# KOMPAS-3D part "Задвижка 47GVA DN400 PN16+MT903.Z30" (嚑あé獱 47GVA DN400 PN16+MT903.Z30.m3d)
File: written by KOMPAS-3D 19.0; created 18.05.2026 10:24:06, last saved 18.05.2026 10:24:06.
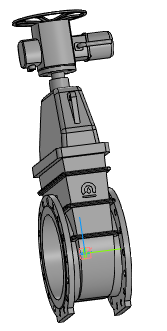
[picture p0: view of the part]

Document properties: Автор: Энергия; Полное имя файла: ..\Задвижка 47GVA DN50_DN1000+MT903.Z\Задвижка 47GVA DN400 PN16+MT903.Z30.a3d

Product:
- Part/product: Задвижка 47GVA DN400 PN16+MT903.Z30
    Масса: 684.343
  - Body: Электропривод MT903.Z20-30
      Масса: 83.2154
  - Body: Задвижка 47GVA DN400 PN16 без исполнительного механизма
      Масса: 601.128

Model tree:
1. Операция без истории:1
2. Операция без истории:2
